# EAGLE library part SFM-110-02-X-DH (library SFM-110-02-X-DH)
0.050"X0.050" SOCKET STRIP ASSEMBLY.
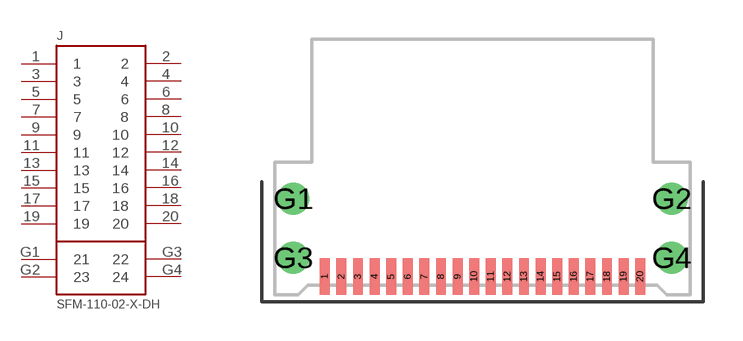
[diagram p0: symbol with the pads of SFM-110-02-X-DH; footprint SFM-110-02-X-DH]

Designator prefix J

## SFM-110-02-X-DH  [SFM-110-02-X-DH]
1  1
2  2
3  3
4  4
5  5
6  6
7  7
8  8
9  9
10  10
11  11
12  12
13  13
14  14
15  15
16  16
17  17
18  18
19  19
20  20
G1  21
G2  23
G3  22
G4  24

## Footprint SFM-110-02-X-DH (pad centres in mm)
0.050"X0.050" SOCKET STRIP ASSEMBLY.
smd 0.381 x 1.397: 1 -6.032,-4.128; 2 -5.397,-4.128; 3 -4.763,-4.128; 4 -4.128,-4.128; 5 -3.493,-4.128; 6 -2.857,-4.128; 7 -2.223,-4.128; 8 -1.587,-4.128; 9 -0.953,-4.128; 10 -0.318,-4.128; 11 0.318,-4.128; 12 0.953,-4.128; 13 1.587,-4.128; 14 2.223,-4.128; 15 2.857,-4.128; 16 3.493,-4.128; 17 4.128,-4.128; 18 4.763,-4.128; 19 5.397,-4.128; 20 6.032,-4.128
drill 0.711 pad 1.143 round: G1 -7.239,-1.143; G2 7.239,-1.143; G3 -7.239,-3.404; G4 7.239,-3.404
